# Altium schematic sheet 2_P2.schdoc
size 307 x 218 mm; Symbol: Drawing-Symbol_A4; Device: Drawing-Symbol_A4; @Project Name: sonos_knobs; @Page Count: 2; @Update Date: 2025-01-13; @Create Date: 2025-01-12; @Schematic Name: Schematic1; @Page No: 2; @Page Name: P2; Company: EasyEDA.com; Version: V1.0; Page Size: A4; @Create Time: 03:45:27; @Update Time: 19:43:57; Width: 1170; Height: 825; Region Start: 1; X Region Count: 6; Y Region Count: 4; Blade Width: 10; Title Block Position: 3; @Board Name: Board1
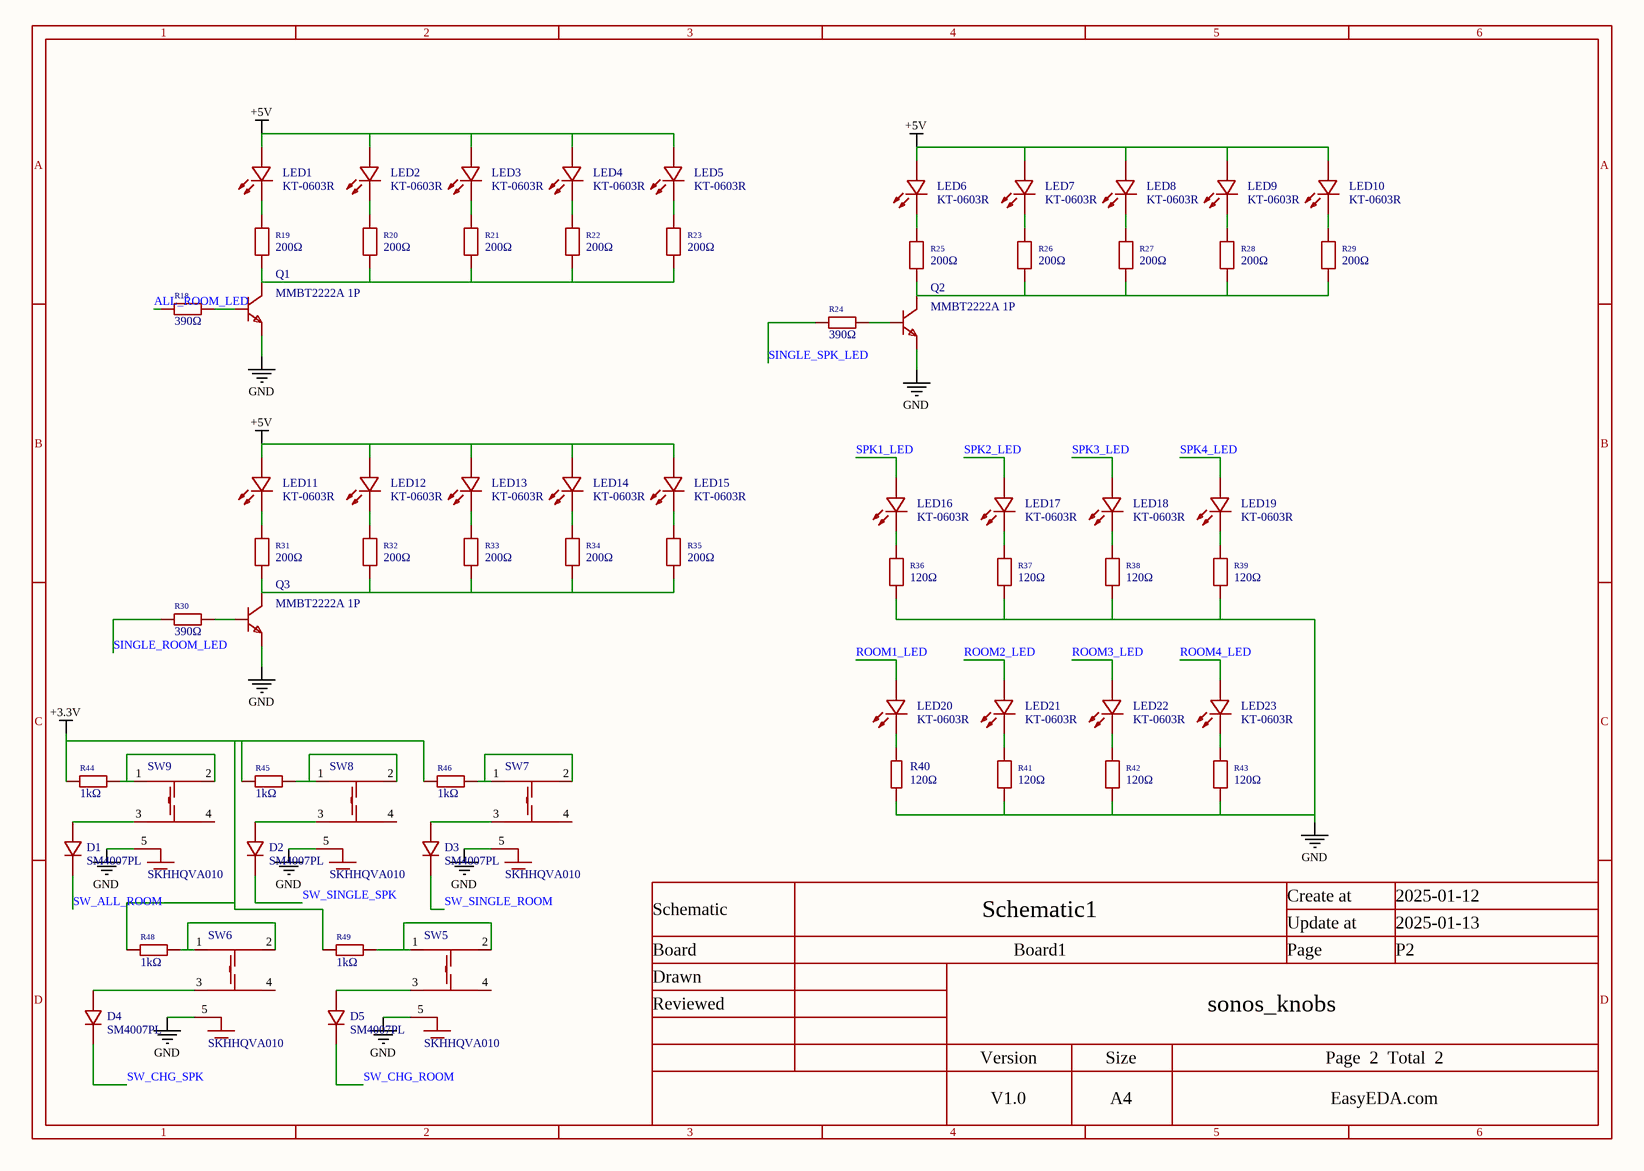
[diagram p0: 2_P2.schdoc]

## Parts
D1  SM4007PL  [SOD-123F_L2.8-W1.8-LS3.7-RD]
D2  SM4007PL  [SOD-123F_L2.8-W1.8-LS3.7-RD]
D3  SM4007PL  [SOD-123F_L2.8-W1.8-LS3.7-RD]
D4  SM4007PL  [SOD-123F_L2.8-W1.8-LS3.7-RD]
D5  SM4007PL  [SOD-123F_L2.8-W1.8-LS3.7-RD]
LED1  KT-0603R  [LED0603-RD]
LED2  KT-0603R  [LED0603-RD]
LED3  KT-0603R  [LED0603-RD]
LED4  KT-0603R  [LED0603-RD]
LED5  KT-0603R  [LED0603-RD]
LED6  KT-0603R  [LED0603-RD]
LED7  KT-0603R  [LED0603-RD]
LED8  KT-0603R  [LED0603-RD]
LED9  KT-0603R  [LED0603-RD]
LED10  KT-0603R  [LED0603-RD]
LED11  KT-0603R  [LED0603-RD]
LED12  KT-0603R  [LED0603-RD]
LED13  KT-0603R  [LED0603-RD]
LED14  KT-0603R  [LED0603-RD]
LED15  KT-0603R  [LED0603-RD]
LED16  KT-0603R  [LED0603-RD]
LED17  KT-0603R  [LED0603-RD]
LED18  KT-0603R  [LED0603-RD]
LED19  KT-0603R  [LED0603-RD]
LED20  KT-0603R  [LED0603-RD]
LED21  KT-0603R  [LED0603-RD]
LED22  KT-0603R  [LED0603-RD]
LED23  KT-0603R  [LED0603-RD]
Q1  MMBT2222A 1P  [SOT-23-3_L2.9-W1.3-P1.90-LS2.4-BR]
Q2  MMBT2222A 1P  [SOT-23-3_L2.9-W1.3-P1.90-LS2.4-BR]
Q3  MMBT2222A 1P  [SOT-23-3_L2.9-W1.3-P1.90-LS2.4-BR]
R18  390Ω  [C0402]
R19  200Ω  [C0402]
R20  200Ω  [C0402]
R21  200Ω  [C0402]
R22  200Ω  [C0402]
R23  200Ω  [C0402]
R24  390Ω  [C0402]
R25  200Ω  [C0402]
R26  200Ω  [C0402]
R27  200Ω  [C0402]
R28  200Ω  [C0402]
R29  200Ω  [C0402]
R30  390Ω  [C0402]
R31  200Ω  [C0402]
R32  200Ω  [C0402]
R33  200Ω  [C0402]
R34  200Ω  [C0402]
R35  200Ω  [C0402]
R36  120Ω  [C0402]
R37  120Ω  [C0402]
R38  120Ω  [C0402]
R39  120Ω  [C0402]
R40  120Ω  [C0402]
R41  120Ω  [C0402]
R42  120Ω  [C0402]
R43  120Ω  [C0402]
R44  1kΩ  [C0402]
R45  1kΩ  [C0402]
R46  1kΩ  [C0402]
R48  1kΩ  [C0402]
R49  1kΩ  [C0402]
SW5  SKHHQVA010  [SW-TH_5P-L6.0-W6.0-P4.50-LS6.5]
SW6  SKHHQVA010  [SW-TH_5P-L6.0-W6.0-P4.50-LS6.5]
SW7  SKHHQVA010  [SW-TH_5P-L6.0-W6.0-P4.50-LS6.5]
SW8  SKHHQVA010  [SW-TH_5P-L6.0-W6.0-P4.50-LS6.5]
SW9  SKHHQVA010  [SW-TH_5P-L6.0-W6.0-P4.50-LS6.5]

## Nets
+3.3V: R44.1 R45.1 R46.1 R48.1 R49.1
+5V: LED1.2(A) LED2.2(A) LED3.2(A) LED4.2(A) LED5.2(A) LED6.2(A) LED7.2(A) LED8.2(A) LED9.2(A) LED10.2(A) LED11.2(A) LED12.2(A) LED13.2(A) LED14.2(A) LED15.2(A)
GND: Q1.2(E) Q2.2(E) Q3.2(E) R36.1 R37.1 R38.1 R39.1 R40.1 R41.1 R42.1 R43.1 SW5.5 SW6.5 SW7.5 SW8.5 SW9.5
ALL_ROOM_LED: R18.1
ROOM1_LED: LED20.2(A)
ROOM2_LED: LED21.2(A)
ROOM3_LED: LED22.2(A)
ROOM4_LED: LED23.2(A)
SINGLE_ROOM_LED: R30.1
SINGLE_SPK_LED: R24.1
SPK1_LED: LED16.2(A)
SPK2_LED: LED17.2(A)
SPK3_LED: LED18.2(A)
SPK4_LED: LED19.2(A)
SW_ALL_ROOM: D1.1(C)
SW_CHG_ROOM: D5.1(C)
SW_CHG_SPK: D4.1(C)
SW_SINGLE_ROOM: D3.1(C)
SW_SINGLE_SPK: D2.1(C)
NetD1_2: D1.2(A) SW9.3
NetD2_2: D2.2(A) SW8.3
NetD3_2: D3.2(A) SW7.3
NetD4_2: D4.2(A) SW6.3
NetD5_2: D5.2(A) SW5.3
NetLED1_1: LED1.1(K) R19.2
NetLED2_1: LED2.1(K) R20.2
NetLED3_1: LED3.1(K) R21.2
NetLED4_1: LED4.1(K) R22.2
NetLED5_1: LED5.1(K) R23.2
NetLED6_1: LED6.1(K) R25.2
NetLED7_1: LED7.1(K) R26.2
NetLED8_1: LED8.1(K) R27.2
NetLED9_1: LED9.1(K) R28.2
NetLED10_1: LED10.1(K) R29.2
NetLED11_1: LED11.1(K) R31.2
NetLED12_1: LED12.1(K) R32.2
NetLED13_1: LED13.1(K) R33.2
NetLED14_1: LED14.1(K) R34.2
NetLED15_1: LED15.1(K) R35.2
NetLED16_1: LED16.1(K) R36.2
NetLED17_1: LED17.1(K) R37.2
NetLED18_1: LED18.1(K) R38.2
NetLED19_1: LED19.1(K) R39.2
NetLED20_1: LED20.1(K) R40.2
NetLED21_1: LED21.1(K) R41.2
NetLED22_1: LED22.1(K) R42.2
NetLED23_1: LED23.1(K) R43.2
NetQ1_1: Q1.1(B) R18.2
NetQ1_3: Q1.3(C) R19.1 R20.1 R21.1 R22.1 R23.1
NetQ2_1: Q2.1(B) R24.2
NetQ2_3: Q2.3(C) R25.1 R26.1 R27.1 R28.1 R29.1
NetQ3_1: Q3.1(B) R30.2
NetQ3_3: Q3.3(C) R31.1 R32.1 R33.1 R34.1 R35.1
NetR44_2: R44.2 SW9.1 SW9.2
NetR45_2: R45.2 SW8.1 SW8.2
NetR46_2: R46.2 SW7.1 SW7.2
NetR48_2: R48.2 SW6.1 SW6.2
NetR49_2: R49.2 SW5.1 SW5.2

Not connected (* = marked no-connect by the designer): SW5 4; SW6 4; SW7 4; SW8 4; SW9 4

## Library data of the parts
D1-D5 = SM4007PL_C64898: Manufacturer: MDD(辰达半导体); Add into BOM: yes; Forward Voltage (Vf@If): 1.1V@1A; Reverse Leakage Current: 10uA@1kV
LED1-LED23 = KT-0603R: Manufacturer: KENTO; Add into BOM: yes; Emitted Color: Red
Q1-Q3 = MMBT2222A 1P: Manufacturer: CJ(江苏长电/长晶); Symbol: MMBT2222A_C8512; Add into BOM: yes; DC Current Gain (hFE@Ic,Vce): 100@150mA,10V; Transition Frequency (fT): 300MHz; Collector Cut-Off Current (Icbo): 10nA; Collector-Emitter Saturation Voltage (VCE(sat)@Ic,Ib): 1V@500mA,50mA
R18 R24 R30 = ERJ2RKF3900X: Manufacturer: PANASONIC(松下); Symbol: 0402WGF1001TCE; Add into BOM: yes; Tolerance: ±1%; Temperature Coefficient: ±100ppm/℃
R19-R23 R25-R29 R31-R35 = CRCW0402200RFKEDHP: Manufacturer: VISHAY(威世); Symbol: ERJ2RKF1500X; Add into BOM: yes; Tolerance: ±1%; Temperature Coefficient: ±100ppm/℃
R36-R39 R41-R43 = 0402WGF1200TCE: Manufacturer: UNI-ROYAL(厚声); Symbol: ERJ2RKF1500X; Add into BOM: yes; Tolerance: ±1%; Temperature Coefficient: ±100ppm/℃
R40 = 0402WGF1200TCE: Manufacturer: UNI-ROYAL(厚声); Add into BOM: yes; Tolerance: ±1%; Temperature Coefficient: ±100ppm/℃
R44-R46 R48 R49 = 0402WGF1001TCE: Manufacturer: UNI-ROYAL(厚声); Add into BOM: yes; Tolerance: ±1%; Temperature Coefficient: ±100ppm/℃
SW5-SW9 = SKHHQVA010: Manufacturer: ALPSALPINE(阿尔卑斯阿尔派); Add into BOM: yes; Circuit: SPST; Actuator Style: Round Button; Contact Current: 50mA; Voltage Rating (DC): 12V; Insulation Resistance: 100MΩ; Actuator/Cap Color: Black; Pin Style: PCPin; Operating Force: 0.98N; Mechanical Life: 100万次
